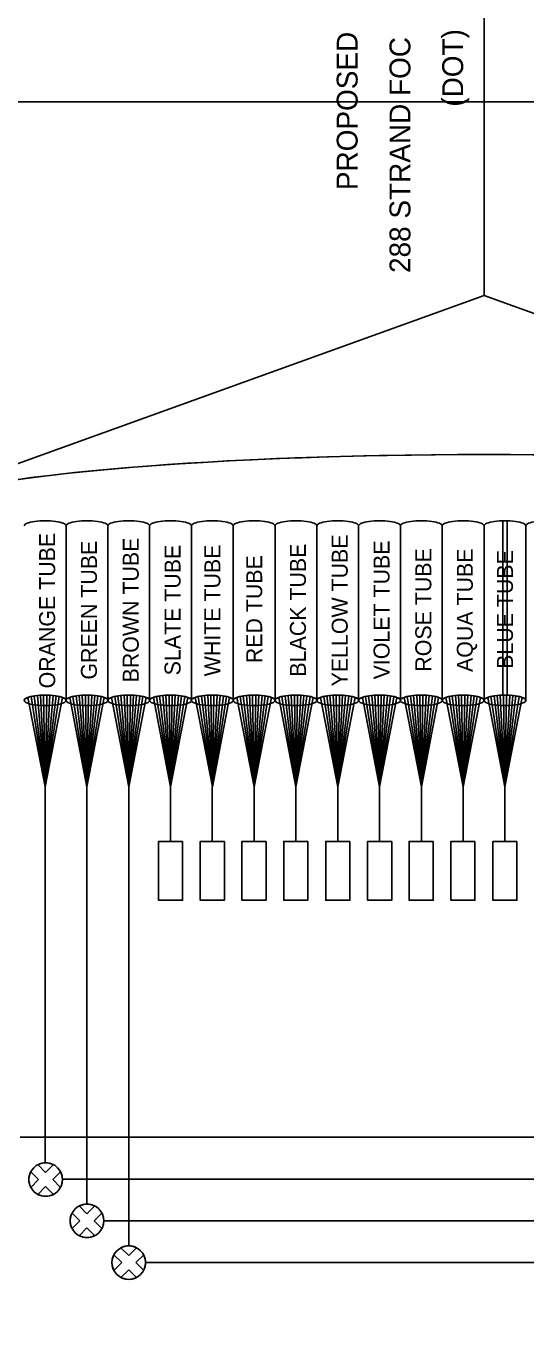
# Model space of a CAD drawing. Extents: x 1805893 to 1833564, y 708898 to 716199.
# Drawn here: x 1832432.6 to 1832504.3, y 714363 to 714550.6 of the extents above; entities that cross this region are included whole.
import ezdxf

# ---------------------------------------------------------------- set-up
doc = ezdxf.new("R2010")
doc.units = 0
doc.layers.add('BR_P_Sub_Hidden', color=7, linetype='Continuous')
doc.layers.add('SH_Data', color=7, linetype='Continuous')

msp = doc.modelspace()

# ---------------------------------------------------------------- linework, layer by layer
at = {"layer": 'BR_P_Sub_Hidden'}
msp.add_lwpolyline([(1832399.8, 714539.7), (1832651.12, 714539.7), (1832651.12, 714279.3), (1832399.8, 714279.3)], close=True, dxfattribs=at)
at = {"layer": 'SH_Data'}
for p, q in [((1832498.32, 714511.85), (1832498.32, 714555.42)), ((1832438.32, 714478.78), (1832438.32, 714453.73)), ((1832438.32, 714453.73), (1832438.32, 714478.78)), ((1832444.32, 714453.73), (1832444.32, 714478.78)), ((1832444.32, 714478.78), (1832444.32, 714453.73)), ((1832450.32, 714453.73), (1832450.32, 714478.78)), ((1832450.32, 714478.78), (1832450.32, 714453.73)), ((1832456.32, 714453.73), (1832456.32, 714478.78)), ((1832456.32, 714478.78), (1832456.32, 714453.73)), ((1832462.32, 714453.73), (1832462.32, 714478.78)), ((1832462.32, 714478.78), (1832462.32, 714453.73)), ((1832468.32, 714453.73), (1832468.32, 714478.78)), ((1832468.32, 714478.78), (1832468.32, 714453.73)), ((1832474.32, 714478.78), (1832474.32, 714453.73)), ((1832474.32, 714453.73), (1832474.32, 714478.78)), ((1832480.32, 714453.73), (1832480.32, 714478.78)), ((1832480.32, 714478.78), (1832480.32, 714453.73)), ((1832480.32, 714478.78), (1832480.32, 714453.73)), ((1832486.32, 714453.73), (1832486.32, 714478.78)), ((1832486.32, 714478.78), (1832486.32, 714453.73)), ((1832492.32, 714453.73), (1832492.32, 714478.78)), ((1832492.32, 714478.78), (1832492.32, 714453.73)), ((1832498.32, 714453.73), (1832498.32, 714478.78)), ((1832498.32, 714478.78), (1832498.32, 714453.73)), ((1832504.32, 714453.73), (1832504.32, 714478.78)), ((1832435.32, 714441.31), (1832432.85, 714454.15)), ((1832435.32, 714441.31), (1832433.3, 714454.28)), ((1832435.32, 714441.31), (1832433.75, 714454.37)), ((1832435.32, 714441.31), (1832434.2, 714454.42)), ((1832435.32, 714441.31), (1832434.65, 714454.46)), ((1832435.32, 714441.31), (1832435.1, 714454.48)), ((1832435.32, 714441.31), (1832435.55, 714454.48)), ((1832435.32, 714441.31), (1832436, 714454.46)), ((1832435.32, 714441.31), (1832436.45, 714454.42)), ((1832435.32, 714441.31), (1832436.9, 714454.37)), ((1832435.32, 714441.31), (1832437.35, 714454.28)), ((1832435.32, 714441.31), (1832437.8, 714454.15)), ((1832441.32, 714441.31), (1832438.85, 714454.15)), ((1832441.32, 714441.31), (1832439.3, 714454.28)), ((1832441.32, 714441.31), (1832439.75, 714454.37)), ((1832441.32, 714441.31), (1832440.2, 714454.42)), ((1832441.32, 714441.31), (1832440.65, 714454.46)), ((1832441.32, 714441.31), (1832441.1, 714454.48)), ((1832441.32, 714441.31), (1832441.55, 714454.48)), ((1832441.32, 714441.31), (1832442, 714454.46)), ((1832441.32, 714441.31), (1832442.45, 714454.42)), ((1832441.32, 714441.31), (1832442.9, 714454.37)), ((1832441.32, 714441.31), (1832443.35, 714454.28)), ((1832441.32, 714441.31), (1832443.8, 714454.15)), ((1832447.32, 714441.31), (1832444.85, 714454.15)), ((1832447.32, 714441.31), (1832445.3, 714454.28)), ((1832447.32, 714441.31), (1832445.75, 714454.37)), ((1832447.32, 714441.31), (1832446.2, 714454.42)), ((1832447.32, 714441.31), (1832446.65, 714454.46)), ((1832447.32, 714441.31), (1832447.1, 714454.48)), ((1832447.32, 714441.31), (1832447.55, 714454.48)), ((1832447.32, 714441.31), (1832448, 714454.46)), ((1832447.32, 714441.31), (1832448.45, 714454.42)), ((1832447.32, 714441.31), (1832448.9, 714454.37)), ((1832447.32, 714441.31), (1832449.35, 714454.28)), ((1832447.32, 714441.31), (1832449.8, 714454.15)), ((1832453.32, 714441.31), (1832450.85, 714454.15)), ((1832453.32, 714441.31), (1832451.3, 714454.28)), ((1832453.32, 714441.31), (1832451.75, 714454.37)), ((1832453.32, 714441.31), (1832452.2, 714454.42)), ((1832453.32, 714441.31), (1832452.65, 714454.46)), ((1832453.32, 714441.31), (1832453.1, 714454.48)), ((1832453.32, 714441.31), (1832453.55, 714454.48)), ((1832453.32, 714441.31), (1832454, 714454.46)), ((1832453.32, 714441.31), (1832454.45, 714454.42)), ((1832453.32, 714441.31), (1832454.9, 714454.37)), ((1832453.32, 714441.31), (1832455.35, 714454.28)), ((1832453.32, 714441.31), (1832455.8, 714454.15)), ((1832459.32, 714441.31), (1832456.85, 714454.15)), ((1832459.32, 714441.31), (1832457.3, 714454.28)), ((1832459.32, 714441.31), (1832457.75, 714454.37)), ((1832459.32, 714441.31), (1832458.2, 714454.42)), ((1832459.32, 714441.31), (1832458.65, 714454.46)), ((1832459.32, 714441.31), (1832459.1, 714454.48)), ((1832459.32, 714441.31), (1832459.55, 714454.48)), ((1832459.32, 714441.31), (1832460, 714454.46)), ((1832459.32, 714441.31), (1832460.45, 714454.42)), ((1832459.32, 714441.31), (1832460.9, 714454.37)), ((1832459.32, 714441.31), (1832461.35, 714454.28)), ((1832459.32, 714441.31), (1832461.8, 714454.15)), ((1832465.32, 714441.31), (1832462.85, 714454.15)), ((1832465.32, 714441.31), (1832463.3, 714454.28)), ((1832465.32, 714441.31), (1832463.75, 714454.37)), ((1832465.32, 714441.31), (1832464.2, 714454.42)), ((1832465.32, 714441.31), (1832464.65, 714454.46)), ((1832465.32, 714441.31), (1832465.1, 714454.48)), ((1832465.32, 714441.31), (1832465.55, 714454.48)), ((1832465.32, 714441.31), (1832466, 714454.46)), ((1832465.32, 714441.31), (1832466.45, 714454.42)), ((1832465.32, 714441.31), (1832466.9, 714454.37)), ((1832465.32, 714441.31), (1832467.35, 714454.28)), ((1832465.32, 714441.31), (1832467.8, 714454.15)), ((1832471.32, 714441.31), (1832468.85, 714454.15)), ((1832471.32, 714441.31), (1832469.3, 714454.28)), ((1832471.32, 714441.31), (1832469.75, 714454.37)), ((1832471.32, 714441.31), (1832470.2, 714454.42)), ((1832471.32, 714441.31), (1832470.65, 714454.46)), ((1832471.32, 714441.31), (1832471.1, 714454.48)), ((1832471.32, 714441.31), (1832471.55, 714454.48)), ((1832471.32, 714441.31), (1832472, 714454.46)), ((1832471.32, 714441.31), (1832472.45, 714454.42)), ((1832471.32, 714441.31), (1832472.9, 714454.37)), ((1832471.32, 714441.31), (1832473.35, 714454.28)), ((1832471.32, 714441.31), (1832473.8, 714454.15)), ((1832477.32, 714441.31), (1832474.85, 714454.15)), ((1832477.32, 714441.31), (1832475.3, 714454.28)), ((1832477.32, 714441.31), (1832475.75, 714454.37)), ((1832477.32, 714441.31), (1832476.2, 714454.42)), ((1832477.32, 714441.31), (1832476.65, 714454.46)), ((1832477.32, 714441.31), (1832477.1, 714454.48)), ((1832477.32, 714441.31), (1832477.55, 714454.48)), ((1832477.32, 714441.31), (1832478, 714454.46)), ((1832477.32, 714441.31), (1832478.45, 714454.42)), ((1832477.32, 714441.31), (1832478.9, 714454.37)), ((1832477.32, 714441.31), (1832479.35, 714454.28)), ((1832477.32, 714441.31), (1832479.8, 714454.15)), ((1832483.32, 714441.31), (1832480.85, 714454.15)), ((1832483.32, 714441.31), (1832481.3, 714454.28)), ((1832483.32, 714441.31), (1832481.75, 714454.37)), ((1832483.32, 714441.31), (1832482.2, 714454.42)), ((1832483.32, 714441.31), (1832482.65, 714454.46)), ((1832483.32, 714441.31), (1832483.1, 714454.48)), ((1832483.32, 714441.31), (1832483.55, 714454.48)), ((1832483.32, 714441.31), (1832484, 714454.46)), ((1832483.32, 714441.31), (1832484.45, 714454.42)), ((1832483.32, 714441.31), (1832484.9, 714454.37)), ((1832483.32, 714441.31), (1832485.35, 714454.28)), ((1832483.32, 714441.31), (1832485.8, 714454.15)), ((1832489.32, 714441.31), (1832486.85, 714454.15)), ((1832489.32, 714441.31), (1832487.3, 714454.28)), ((1832489.32, 714441.31), (1832487.75, 714454.37)), ((1832489.32, 714441.31), (1832488.2, 714454.42)), ((1832489.32, 714441.31), (1832488.65, 714454.46)), ((1832489.32, 714441.31), (1832489.1, 714454.48)), ((1832489.32, 714441.31), (1832489.55, 714454.48)), ((1832489.32, 714441.31), (1832490, 714454.46)), ((1832489.32, 714441.31), (1832490.45, 714454.42)), ((1832489.32, 714441.31), (1832490.9, 714454.37)), ((1832489.32, 714441.31), (1832491.35, 714454.28)), ((1832489.32, 714441.31), (1832491.8, 714454.15)), ((1832495.32, 714441.31), (1832492.85, 714454.15)), ((1832495.32, 714441.31), (1832493.3, 714454.28)), ((1832495.32, 714441.31), (1832493.75, 714454.37)), ((1832495.32, 714441.31), (1832494.2, 714454.42)), ((1832495.32, 714441.31), (1832494.65, 714454.46)), ((1832495.32, 714441.31), (1832495.1, 714454.48)), ((1832495.32, 714441.31), (1832495.55, 714454.48)), ((1832495.32, 714441.31), (1832496, 714454.46)), ((1832495.32, 714441.31), (1832496.45, 714454.42)), ((1832495.32, 714441.31), (1832496.9, 714454.37)), ((1832495.32, 714441.31), (1832497.35, 714454.28)), ((1832495.32, 714441.31), (1832497.8, 714454.15)), ((1832501.32, 714441.31), (1832498.85, 714454.15)), ((1832501.32, 714441.31), (1832499.3, 714454.28)), ((1832501.32, 714441.31), (1832499.75, 714454.37)), ((1832501.32, 714441.31), (1832500.2, 714454.42)), ((1832501.32, 714441.31), (1832500.65, 714454.46)), ((1832501.32, 714441.31), (1832501.1, 714454.48)), ((1832501.32, 714441.31), (1832501.55, 714454.48)), ((1832501.32, 714441.31), (1832502, 714454.46)), ((1832501.32, 714441.31), (1832502.45, 714454.42)), ((1832501.32, 714441.31), (1832502.9, 714454.37)), ((1832501.32, 714441.31), (1832503.35, 714454.28)), ((1832501.32, 714441.31), (1832503.8, 714454.15)), ((1832435.32, 714441.31), (1832435.32, 714387.32)), ((1832441.32, 714441.31), (1832441.32, 714381.39)), ((1832447.32, 714441.31), (1832447.32, 714375.39)), ((1832453.32, 714441.31), (1832453.32, 714433.48)), ((1832459.29, 714441.31), (1832459.29, 714433.48)), ((1832465.32, 714433.48), (1832465.32, 714441.31)), ((1832471.32, 714441.31), (1832471.32, 714433.48)), ((1832477.32, 714441.31), (1832477.32, 714433.48)), ((1832483.32, 714441.31), (1832483.32, 714433.48)), ((1832489.32, 714441.31), (1832489.32, 714433.48)), ((1832495.32, 714441.31), (1832495.33, 714433.48)), ((1832501.32, 714433.48), (1832501.32, 714441.31)), ((1832587.03, 714390.98), (1832431.74, 714390.98)), ((1832435.39, 714385.93), (1832434.27, 714387.05)), ((1832434.27, 714387.05), (1832435.39, 714385.93)), ((1832436.51, 714387.05), (1832435.39, 714385.93)), ((1832435.39, 714385.93), (1832436.51, 714387.05)), ((1832434.37, 714384.91), (1832433.25, 714386.03)), ((1832434.37, 714384.91), (1832433.25, 714386.03)), ((1832434.37, 714384.91), (1832433.25, 714383.79)), ((1832433.25, 714383.79), (1832434.37, 714384.91)), ((1832437.52, 714386.03), (1832436.41, 714384.91)), ((1832437.52, 714386.03), (1832436.41, 714384.91)), ((1832437.52, 714383.79), (1832436.41, 714384.91)), ((1832436.41, 714384.91), (1832437.52, 714383.79)), ((1832587.03, 714384.98), (1832437.8, 714384.98)), ((1832435.39, 714383.89), (1832434.27, 714382.78)), ((1832435.39, 714383.89), (1832434.27, 714382.78)), ((1832436.51, 714382.78), (1832435.39, 714383.89)), ((1832436.51, 714382.78), (1832435.39, 714383.89)), ((1832441.32, 714379.99), (1832440.2, 714381.11)), ((1832440.2, 714381.11), (1832441.32, 714379.99)), ((1832442.44, 714381.11), (1832441.32, 714379.99)), ((1832441.32, 714379.99), (1832442.44, 714381.11)), ((1832440.31, 714378.98), (1832439.19, 714380.1)), ((1832440.31, 714378.98), (1832439.19, 714380.1)), ((1832443.46, 714380.1), (1832442.34, 714378.98)), ((1832443.46, 714380.1), (1832442.34, 714378.98)), ((1832440.31, 714378.98), (1832439.19, 714377.86)), ((1832439.19, 714377.86), (1832440.31, 714378.98)), ((1832441.32, 714377.96), (1832440.2, 714376.84)), ((1832441.32, 714377.96), (1832440.2, 714376.84)), ((1832442.44, 714376.84), (1832441.32, 714377.96)), ((1832442.44, 714376.84), (1832441.32, 714377.96)), ((1832443.46, 714377.86), (1832442.34, 714378.98)), ((1832442.34, 714378.98), (1832443.46, 714377.86)), ((1832587.03, 714378.98), (1832443.74, 714378.98)), ((1832446.31, 714372.98), (1832445.19, 714374.1)), ((1832446.31, 714372.98), (1832445.19, 714374.1)), ((1832447.32, 714373.99), (1832446.2, 714375.11)), ((1832446.2, 714375.11), (1832447.32, 714373.99)), ((1832448.44, 714375.11), (1832447.32, 714373.99)), ((1832447.32, 714373.99), (1832448.44, 714375.11)), ((1832449.46, 714374.1), (1832448.34, 714372.98)), ((1832449.46, 714374.1), (1832448.34, 714372.98)), ((1832446.31, 714372.98), (1832445.19, 714371.86)), ((1832445.19, 714371.86), (1832446.31, 714372.98)), ((1832447.32, 714371.96), (1832446.2, 714370.84)), ((1832447.32, 714371.96), (1832446.2, 714370.84)), ((1832448.44, 714370.84), (1832447.32, 714371.96)), ((1832448.44, 714370.84), (1832447.32, 714371.96)), ((1832449.46, 714371.86), (1832448.34, 714372.98)), ((1832448.34, 714372.98), (1832449.46, 714371.86)), ((1832587.03, 714372.98), (1832449.73, 714372.98))]:
    msp.add_line(p, q, dxfattribs=at)
msp.add_lwpolyline([(1832416.13, 714482.25), (1832498.32, 714511.85), (1832580.52, 714482.25)], dxfattribs=at)
msp.add_lwpolyline([(1832416.13, 714482.25), (1832498.32, 714511.85), (1832580.52, 714482.25)], dxfattribs=at)
for points in [[(1832501.02, 714479.53), (1832501.02, 714454.48), (1832501.62, 714454.48), (1832501.62, 714479.53)], [(1832455.05, 714433.48), (1832451.59, 714433.48), (1832451.59, 714425.03), (1832455.05, 714425.03)], [(1832461.05, 714433.48), (1832457.59, 714433.48), (1832457.59, 714425.03), (1832461.05, 714425.03)], [(1832467.02, 714433.48), (1832463.56, 714433.48), (1832463.56, 714425.03), (1832467.02, 714425.03)], [(1832473.02, 714433.48), (1832469.56, 714433.48), (1832469.56, 714425.03), (1832473.02, 714425.03)], [(1832479.06, 714433.48), (1832475.6, 714433.48), (1832475.6, 714425.03), (1832479.06, 714425.03)], [(1832485.06, 714433.48), (1832481.6, 714433.48), (1832481.6, 714425.03), (1832485.06, 714425.03)], [(1832491.02, 714433.48), (1832487.56, 714433.48), (1832487.56, 714425.03), (1832491.02, 714425.03)], [(1832497.02, 714433.48), (1832493.56, 714433.48), (1832493.56, 714425.03), (1832497.02, 714425.03)], [(1832503.05, 714433.48), (1832499.59, 714433.48), (1832499.59, 714425.03), (1832503.05, 714425.03)]]:
    msp.add_lwpolyline(points, close=True, dxfattribs=at)
for centre in [(1832435.39, 714384.91), (1832441.32, 714378.98), (1832447.32, 714372.98)]:
    msp.add_circle(centre, 2.41, dxfattribs=at)
for centre, start, end in [((1832435.39, 714384.91), 62.353, 117.647), ((1832435.39, 714384.91), 152.353, 207.647), ((1832435.39, 714384.91), 332.353, 27.647), ((1832435.39, 714384.91), 242.353, 297.647), ((1832441.32, 714378.98), 62.353, 117.647), ((1832441.32, 714378.98), 152.353, 207.647), ((1832441.32, 714378.98), 332.353, 27.647), ((1832441.32, 714378.98), 242.353, 297.647), ((1832447.32, 714372.98), 62.353, 117.647), ((1832447.32, 714372.98), 152.353, 207.647), ((1832447.32, 714372.98), 332.353, 27.647), ((1832447.32, 714372.98), 242.353, 297.647)]:
    msp.add_arc(centre, 2.41, start, end, dxfattribs=at)
for centre, major_axis, ratio, start_param, end_param in [((1832498.32, 714479.38), (86.09, 0), 0.112175, 5.702888, 10.005075), ((1832498.32, 714479.38), (86.09, 0), 0.112175, 5.702888, 10.005075), ((1832498.32, 714479.38), (86.09, 0), 0.112175, 0.302036, 2.839557), ((1832435.32, 714478.78), (3, 0), 0.25, 0, 3.141593), ((1832435.32, 714478.78), (3, 0), 0.25, 0, 3.141593), ((1832441.32, 714478.78), (3, 0), 0.25, 0, 3.141593), ((1832441.32, 714478.78), (3, 0), 0.25, 0, 3.141593), ((1832447.32, 714478.78), (3, 0), 0.25, 0, 3.141593), ((1832447.32, 714478.78), (3, 0), 0.25, 0, 3.141593), ((1832453.32, 714478.78), (3, 0), 0.25, 0, 3.141593), ((1832453.32, 714478.78), (3, 0), 0.25, 0, 3.141593), ((1832459.32, 714478.78), (3, 0), 0.25, 0, 3.141593), ((1832459.32, 714478.78), (3, 0), 0.25, 0, 3.141593), ((1832465.32, 714478.78), (3, 0), 0.25, 0, 3.141593), ((1832465.32, 714478.78), (3, 0), 0.25, 0, 3.141593), ((1832471.32, 714478.78), (3, 0), 0.25, 0, 3.141593), ((1832471.32, 714478.78), (3, 0), 0.25, 0, 3.141593), ((1832477.32, 714478.78), (3, 0), 0.25, 0, 3.141593), ((1832477.32, 714478.78), (3, 0), 0.25, 0, 3.141593), ((1832483.32, 714478.78), (3, 0), 0.25, 0, 3.141593), ((1832483.32, 714478.78), (3, 0), 0.25, 0, 3.141593), ((1832489.32, 714478.78), (3, 0), 0.25, 0, 3.141593), ((1832489.32, 714478.78), (3, 0), 0.25, 0, 3.141593), ((1832495.32, 714478.78), (3, 0), 0.25, 0, 3.141593), ((1832495.32, 714478.78), (3, 0), 0.25, 0, 3.141593), ((1832501.32, 714478.78), (3, 0), 0.25, 0, 3.141593), ((1832501.32, 714478.78), (3, 0), 0.25, 0, 3.141593), ((1832507.32, 714478.78), (3, 0), 0.25, 0, 3.141593), ((1832435.32, 714453.73), (3, 0), 0.25, 0, 3.141593), ((1832441.32, 714453.73), (3, 0), 0.25, 0, 3.141593), ((1832447.32, 714453.73), (3, 0), 0.25, 0, 3.141593), ((1832453.32, 714453.73), (3, 0), 0.25, 0, 3.141593), ((1832459.32, 714453.73), (3, 0), 0.25, 0, 3.141593), ((1832465.32, 714453.73), (3, 0), 0.25, 0, 3.141593), ((1832471.32, 714453.73), (3, 0), 0.25, 0, 3.141593), ((1832477.32, 714453.73), (3, 0), 0.25, 0, 3.141593), ((1832483.32, 714453.73), (3, 0), 0.25, 0, 3.141593), ((1832489.32, 714453.73), (3, 0), 0.25, 0, 3.141593), ((1832495.32, 714453.73), (3, 0), 0.25, 0, 3.141593), ((1832501.32, 714453.73), (3, 0), 0.25, 0, 3.141593)]:
    msp.add_ellipse(centre, major_axis=major_axis, ratio=ratio, start_param=start_param, end_param=end_param, dxfattribs=at)
for centre in [(1832435.32, 714453.73), (1832441.32, 714453.73), (1832447.32, 714453.73), (1832453.32, 714453.73), (1832459.32, 714453.73), (1832465.32, 714453.73), (1832471.32, 714453.73), (1832477.32, 714453.73), (1832483.32, 714453.73), (1832489.32, 714453.73), (1832495.32, 714453.73), (1832501.32, 714453.73)]:
    msp.add_ellipse(centre, major_axis=(3, 0), ratio=0.25, dxfattribs=at)

# ---------------------------------------------------------------- texts
for s, height, p in [('(DOT)', 3, (1832495.32, 714538.99)), ('PROPOSED', 3, (1832480.17, 714527.01)), ('288 STRAND FOC', 3, (1832487.75, 714515.11)), ('ORANGE TUBE', 2.2947, (1832436.75, 714455.45)), ('GREEN TUBE', 2.295, (1832442.75, 714456.71)), ('BROWN TUBE', 2.295, (1832448.75, 714456.3)), ('YELLOW TUBE', 2.2947, (1832478.75, 714455.73)), ('VIOLET TUBE', 2.2947, (1832484.75, 714456.74)), ('SLATE TUBE', 2.295, (1832454.75, 714457.32)), ('WHITE TUBE', 2.295, (1832460.47, 714457.18)), ('BLACK TUBE', 2.295, (1832472.75, 714457.14)), ('ROSE TUBE', 2.295, (1832490.75, 714457.85)), ('AQUA TUBE', 2.295, (1832496.71, 714457.8)), ('BLUE TUBE', 2.295, (1832502.47, 714458.25)), ('RED TUBE', 2.295, (1832466.47, 714459.06))]:
    msp.add_text(s, height=height, rotation=90, dxfattribs=at).set_placement(p)

doc.saveas('drawing.dxf')
